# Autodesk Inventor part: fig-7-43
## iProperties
Shininess: 77.0
Length Units: 11269
Angle Units: 11279
Time Units: 11290
Mass Units: 11283
Length Display Precision: 3
Angle Display Precision: 2
Created: 2002-01
Part Number: fig-7-43
Document SubType Name: Modeling
Designer: ***
Density: 1 g/cm^3
Density: 0.0
Volumn: 0.0
Area: 0.0
PropertySet Name: Model Information
Control State: 0
Master: False
Checked Out: False
Author: ***
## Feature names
1. Extrusion1
2. Shell3
